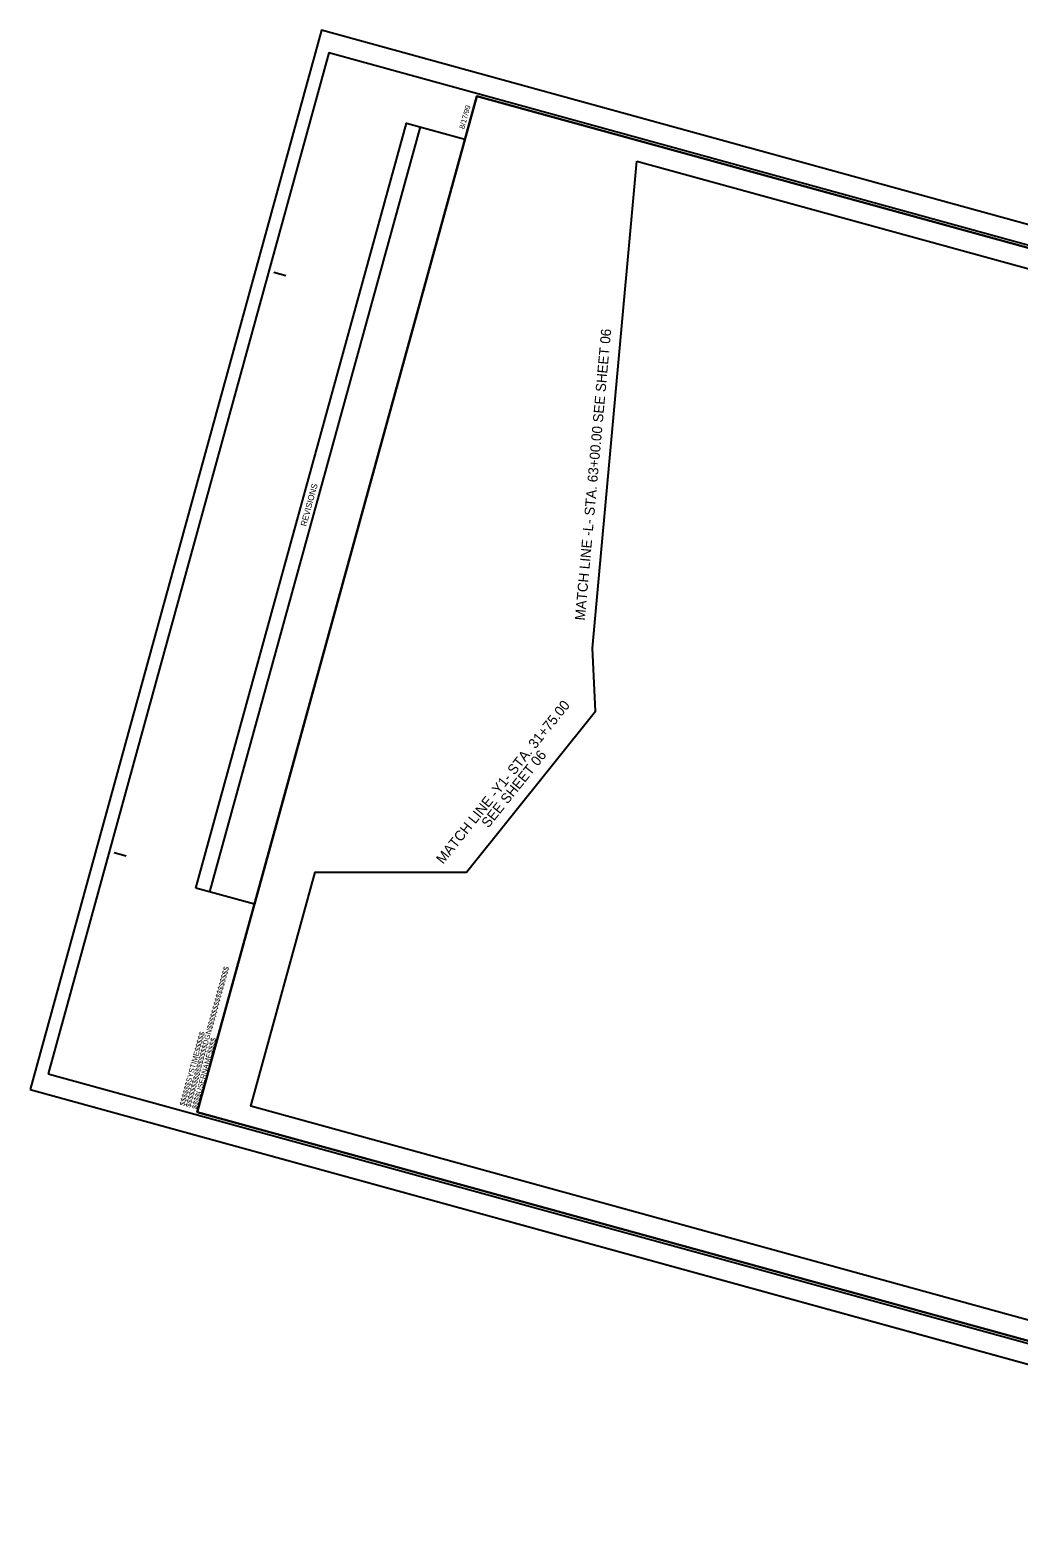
# Model space of a CAD drawing. Extents: x 1641192 to 2864602, y 841295 to 973236.
# Drawn here: x 1641192 to 1642177, y 841295 to 842798 of the extents above; entities that cross this region are included whole.
import ezdxf

# ---------------------------------------------------------------- set-up
doc = ezdxf.new("R2010")
doc.units = 0
for name, color, linetype in [('Matchline', 7, 'Continuous'), ('Matchline Text', 7, 'Continuous'), ('Sheet Block Revision CELL', 7, 'Continuous'), ('Sheet Clip Boundary CELL', 7, 'Continuous'), ('Sheet Cutting Line CELL', 7, 'Continuous'), ('Sheet Plan CELL', 7, 'Continuous'), ('Sheet Plot Border Inside CELL', 7, 'Continuous'), ('Sheet Plot Border Outside CELL', 7, 'Continuous')]:
    doc.layers.add(name, color=color, linetype=linetype)

msp = doc.modelspace()

# ---------------------------------------------------------------- linework, layer by layer
at = {"layer": 'Matchline'}
msp.add_line((1641627.1, 841958.8), (1641755.5, 842119.2), dxfattribs=at)
msp.add_lwpolyline([(1641476.3, 841958.8), (1641627.1, 841958.8), (1641755.5, 842119.2), (1641752.4, 842181.8), (1641796.6, 842667.3)], dxfattribs=at)
at = {"layer": 'Sheet Block Revision CELL'}
msp.add_line((1641371.3, 841939), (1641581.1, 842701.3), dxfattribs=at)
msp.add_lwpolyline([(1641357.3, 841942.8), (1641567.1, 842705.2), (1641625.4, 842689.1), (1641415.7, 841926.8)], close=True, dxfattribs=at)
at = {"layer": 'Sheet Clip Boundary CELL'}
msp.add_line((1641796.6, 842667.3), (1642584.6, 842450.4), dxfattribs=at)
msp.add_lwpolyline([(1642834.8, 842332.3), (1642796.6, 842193.5), (1642979.1, 842143.2), (1642931.9, 841980.8), (1642684.7, 842016.9), (1642616.5, 841780.2), (1642867.9, 841712.2), (1642769.9, 841383), (1642620.7, 841424), (1642612.8, 841395.1), (1641412.1, 841725.5), (1641476.3, 841958.8), (1641627.1, 841958.8), (1641755.5, 842119.2), (1641752.4, 842181.8), (1641796.6, 842667.3)], dxfattribs=at)
at = {"layer": 'Sheet Cutting Line CELL'}
for p, q in [((1641482.6, 842797.7), (1641192.1, 841742)), ((1641192.1, 841742), (1642815.3, 841295.3))]:
    msp.add_line(p, q, dxfattribs=at)
at = {"layer": 'Sheet Plan CELL'}
for p, q in [((1641637.2, 842731.9), (1641637.2, 842731.9)), ((1641435, 842556.7), (1641447, 842553.4)), ((1641275.8, 841978.2), (1641287.9, 841974.9)), ((1641358.6, 841719.5), (1641358.6, 841719.5))]:
    msp.add_line(p, q, dxfattribs=at)
for points in [[(1643083.5, 842333.9), (1641637.2, 842731.9), (1641358.6, 841719.5), (1642804.8, 841321.5)], [(1641358.6, 841719.5), (1641637.2, 842731.9), (1642890.6, 842387), (1642850.8, 842242.3), (1643043.6, 842189.2), (1642804.8, 841321.5)]]:
    msp.add_lwpolyline(points, close=True, dxfattribs=at)
at = {"layer": 'Sheet Plot Border Inside CELL'}
msp.add_lwpolyline([(1641209.9, 841757.8), (1642816.2, 841315.8), (1643096.2, 842333), (1641489.9, 842775)], close=True, dxfattribs=at)
at = {"layer": 'Sheet Plot Border Outside CELL'}
msp.add_lwpolyline([(1641192.1, 841742), (1642815.3, 841295.3), (1643105.8, 842351.1), (1641482.6, 842797.7)], close=True, dxfattribs=at)
msp.add_lwpolyline([(1641192.1, 841742), (1642815.3, 841295.3), (1643105.8, 842351.1), (1641482.6, 842797.7)], close=True, dxfattribs=at)

# ---------------------------------------------------------------- texts
at = {"layer": 'Matchline Text'}
for s, rotation, p in [('MATCH LINE -L- STA. 63+00.00 SEE SHEET 06', 84.8005, (1641744.8, 842209.2)), ('MATCH LINE -Y1- STA. 31+75.00', 51.3193, (1641603.6, 841966.1)), ('SEE SHEET 06', 51.3193, (1641648.7, 842002.1))]:
    msp.add_text(s, height=10, rotation=rotation, dxfattribs=at).set_placement(p)
at = {"layer": 'Sheet Block Revision CELL'}
msp.add_text('REVISIONS', height=6, rotation=74.6135, dxfattribs=at).set_placement((1641467.2, 842302.8))
at = {"layer": 'Sheet Plan CELL'}
for s, p in [('8/17/99', (1641624.7, 842698.8)), ('$$$$$$$$$$$$$$$$DGN$$$$$$$$$$$$$$$$', (1641351.9, 841723.8)), ('$$$$$$SYSTIME$$$$$', (1641346, 841725.4)), ('$$$$USERNAME$$$$', (1641358.2, 841722.1))]:
    msp.add_text(s, height=5.25, rotation=74.6135, dxfattribs=at).set_placement(p)

doc.saveas('drawing.dxf')
